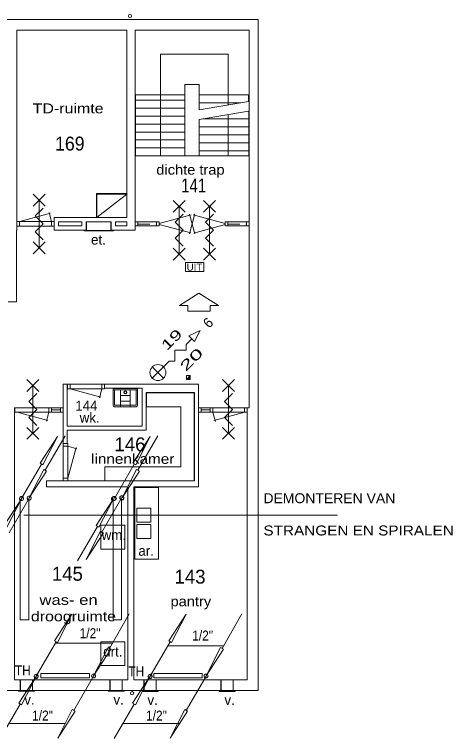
# Model space of a CAD drawing. Extents: x 295824 to 414724, y 24924 to 109024.
# Drawn here: x 326087 to 337101, y 61088 to 79286 of the extents above; entities that cross this region are included whole.
import ezdxf
from ezdxf.enums import TextEntityAlignment as Align

# ---------------------------------------------------------------- set-up
doc = ezdxf.new("R2010")
doc.units = 0
doc.header["$LTSCALE"] = 100
doc.linetypes.add('MEDIUM_DASHED', pattern=[4.5, 3, -1.5])
doc.layers.add('16', color=7, linetype='Continuous', lineweight=13)
doc.layers.add('61', color=7, linetype='Continuous', lineweight=13)

msp = doc.modelspace()

# ---------------------------------------------------------------- hatches: boundary and pattern name
at = {"layer": '61'}
msp.add_hatch(color=256, dxfattribs=at).paths.add_polyline_path([(330408.1, 70115.6), (330508.1, 70215.6), (330508.1, 70115.6)])

# ---------------------------------------------------------------- linework, layer by layer
at = {"layer": '16'}
for p, q in [((327358.8, 68694.8), (326858.8, 67828.8)), ((329690.7, 68694.8), (329190.7, 67828.8)), ((326266.2, 67121.5), (326766.2, 67987.5)), ((328598.2, 67121.5), (329098.2, 67987.5)), ((326453.4, 67125.5), (325953.4, 66259.5)), ((328785.3, 67142.2), (328285.3, 66276.2)), ((326326.3, 66702.7), (334210.4, 66702.7)), ((327675.2, 65554.4), (328175.2, 66420.4)), ((328974.5, 64220.2), (328474.5, 63354.2)), ((331804.8, 64220.2), (331304.8, 63354.2)), ((326632.7, 62655.3), (327132.7, 63521.3)), ((329501.3, 62655.3), (330001.3, 63521.3)), ((327134.2, 63488.1), (328533.4, 63488.1)), ((329943.6, 63420.8), (331342.7, 63420.8)), ((328076.8, 62658.9), (327576.8, 61792.9)), ((330904.3, 62658.9), (330404.3, 61792.9)), ((325729.6, 61087.9), (326229.6, 61953.9)), ((328592.5, 61087.9), (329092.5, 61953.9)), ((325968.1, 61468.4), (327367.3, 61468.4)), ((328816.4, 61468.4), (330215.5, 61468.4))]:
    msp.add_line(p, q, dxfattribs=at)
for points in [[(327166.2, 68680.5), (326802.2, 67966.5), (326730.2, 68008.5)], [(329498.2, 68680.5), (329134.2, 67966.5), (329062.2, 68008.5)], [(326458.8, 67135.8), (326822.8, 67849.8), (326894.8, 67807.8)], [(328790.7, 67135.8), (329154.7, 67849.8), (329226.7, 67807.8)], [(326260, 67113.4), (325896, 66399.4), (325824, 66441.4)], [(328575.2, 67113.4), (328211.2, 66399.4), (328139.2, 66441.4)], [(327885.3, 65583.2), (328249.3, 66297.2), (328321.3, 66255.2)], [(327532.7, 64214.3), (327168.7, 63500.3), (327096.7, 63542.3)], [(330401.3, 64214.3), (330037.3, 63500.3), (329965.3, 63542.3)], [(328074.5, 62661.2), (328438.5, 63375.2), (328510.5, 63333.2)], [(330904.8, 62661.2), (331268.8, 63375.2), (331340.8, 63333.2)], [(326629.6, 62646.9), (326265.6, 61932.9), (326193.6, 61974.9)], [(326752.7, 62616.5), (327969.4, 62616.5), (327969.4, 62723.7), (326752.7, 62723.7)], [(329492.5, 62646.9), (329128.5, 61932.9), (329056.5, 61974.9)], [(329590.7, 62616.5), (330807.4, 62616.5), (330807.4, 62723.7), (329590.7, 62723.7)], [(327176.8, 61099.9), (327540.8, 61813.9), (327612.8, 61771.9)], [(330004.3, 61099.9), (330368.3, 61813.9), (330440.3, 61771.9)]]:
    msp.add_lwpolyline(points, close=True, dxfattribs=at)
for points in [[(326232.5, 67104.9), (326232.5, 64071.6), (326449.1, 64071.6), (326449.1, 67088.2)], [(328564.5, 67104.9), (328564.5, 64071.6), (328781, 64071.6), (328781, 67088.2)]]:
    msp.add_lwpolyline(points, dxfattribs=at)
for centre in [(326259.9, 67113.1), (326266.2, 67121.2), (326453.4, 67125.8), (326458.8, 67136.1), (328575.2, 67113.1), (328598.1, 67121.2), (328785.3, 67142.5), (328790.7, 67136.1), (326629.6, 62646.6), (326632.7, 62655), (328074.5, 62661.5), (328076.8, 62659.2), (329492.5, 62646.6), (329501.3, 62655), (330904.3, 62659.2), (330904.8, 62661.5)]:
    msp.add_circle(centre, 50, dxfattribs=at)
at = {"layer": '61'}
for p, q in [((332210.1, 79160.8), (332210.1, 62296.5)), ((330368.9, 77267.8), (330368.9, 77525.8)), ((330368.9, 77525.8), (330732.6, 77525.8)), ((330732.6, 77267.8), (330732.6, 77525.8)), ((331972.5, 77267.8), (330732.6, 77267.8)), ((331972.5, 77100.5), (331972.5, 77267.8)), ((329129, 77131.4), (330368.9, 77131.4)), ((330732.6, 76889.3), (331972.5, 77100.5)), ((331780.5, 77067.8), (330732.6, 77067.8)), ((329129, 76931.4), (330368.9, 76931.4)), ((330729.7, 76643), (331972.5, 76854.7)), ((329129, 76731.4), (330368.9, 76731.4)), ((331975.6, 76659.4), (330826.3, 76659.4)), ((331459.8, 76767.4), (331459.8, 75733.3)), ((329129, 76531.4), (330368.9, 76531.4)), ((331975.6, 76459.4), (330729.7, 76459.4)), ((329129, 76331.4), (330368.9, 76331.4)), ((331975.6, 76259.4), (330729.7, 76259.4)), ((329129, 76131.4), (330368.9, 76131.4)), ((329129, 75931.4), (330368.9, 75931.4)), ((331975.6, 76059.4), (330729.7, 76059.4)), ((329129, 75731.4), (330368.9, 75731.4)), ((331975.6, 75859.4), (330729.7, 75859.4)), ((326857.7, 74771.3), (326557.7, 74471.3)), ((326557.7, 74771.3), (326857.7, 74471.3)), ((326707.7, 73421.3), (326707.7, 74621.3)), ((328910.1, 74785.8), (328145.1, 74785.8)), ((328145.1, 74785.8), (328145.1, 74185.8)), ((328910.1, 74770.8), (328160.1, 74770.8)), ((328160.1, 74770.8), (328160.1, 74185.8)), ((328908.7, 74765.7), (328165.8, 74191.8)), ((330376.8, 74613.9), (330076.8, 74313.9)), ((330076.8, 74613.9), (330376.8, 74313.9)), ((331143.5, 74613.9), (330843.5, 74313.9)), ((330843.5, 74613.9), (331143.5, 74313.9)), ((330226.8, 73263.9), (330226.8, 74463.9)), ((330993.5, 73263.9), (330993.5, 74463.9)), ((326218.7, 74082.5), (326991.5, 74289.6)), ((327017.1, 74083.1), (326956.4, 74310)), ((330621.8, 73771.1), (330488.5, 74268.5)), ((330489.1, 73776), (330623.8, 74278.7)), ((326142.6, 73967.9), (326142.6, 74081.9)), ((326151.2, 74081.9), (327086.5, 74081.9)), ((326210.9, 73967.9), (326210.9, 74081.9)), ((327019.5, 73967.9), (327019.5, 74081.9)), ((327086.5, 73967.9), (327086.5, 74081.9)), ((328910.1, 74185.8), (327087.4, 74185.8)), ((327087.4, 73865.8), (327087.4, 74185.8)), ((327196.2, 73975.8), (327196.2, 74075.8)), ((327780.1, 74075.8), (327196.2, 74075.8)), ((327780.1, 73975.8), (327780.1, 74075.8)), ((327890.1, 73865.8), (327890.1, 74075.8)), ((328520.1, 74075.8), (327890.1, 74075.8)), ((327895, 73859.2), (327895, 74070.9)), ((327895, 74070.9), (328510.1, 74070.9)), ((328510.1, 73859.2), (328510.1, 74070.9)), ((328520.1, 73865.8), (328520.1, 74075.8)), ((328908.2, 74075.8), (328630.1, 74075.8)), ((328630.1, 73975.8), (328630.1, 74075.8)), ((328908.2, 73975.8), (328908.2, 74075.8)), ((329120.8, 74071.5), (329723.3, 74071.5)), ((329186.3, 73971.5), (329186.3, 74071.5)), ((329657.7, 73971.5), (329657.7, 74071.5)), ((329723.3, 73971.5), (329723.3, 74071.5)), ((329725.3, 74030.5), (330529.4, 74246)), ((330578.4, 74246), (331383.5, 74030.3)), ((331384.7, 73971.5), (331384.7, 74071.5)), ((331384.7, 74071.5), (331990.1, 74071.5)), ((331451.5, 73971.6), (331451.5, 74070.6)), ((331923.1, 73971.2), (331923.1, 74071.2)), ((327086.5, 73967.9), (326151.2, 73967.9)), ((327196.2, 73975.8), (327780.1, 73975.8)), ((328630.1, 73975.8), (328908.2, 73975.8)), ((329120.8, 73971.5), (329723.3, 73971.5)), ((329723.4, 74007.3), (330517.1, 73794.6)), ((330593.7, 73792.7), (331383.5, 74004.3)), ((331384.7, 73971.5), (331990.1, 73971.5)), ((326141.5, 72065.8), (326141.5, 73865.8)), ((327087.4, 73865.8), (327890.1, 73865.8)), ((327840.7, 73858.9), (328577.6, 73858.9)), ((327840.7, 73848.9), (327840.7, 73858.9)), ((327840.7, 73848.9), (328577.6, 73848.9)), ((328520.1, 73865.8), (329120.1, 73865.8)), ((328577.6, 73848.9), (328577.6, 73858.9)), ((331990.1, 73865.8), (331990.1, 69402.2)), ((326857.7, 73571.3), (326557.7, 73271.3)), ((326557.7, 73571.3), (326857.7, 73271.3)), ((330376.8, 73413.9), (330076.8, 73113.9)), ((330076.8, 73413.9), (330376.8, 73113.9)), ((331143.5, 73413.9), (330843.5, 73113.9)), ((330843.5, 73413.9), (331143.5, 73113.9)), ((325931.5, 72065.8), (326141.5, 72065.8)), ((329835.6, 70144.4), (329552.8, 70427.2)), ((326700.5, 70108.8), (326400.5, 69808.8)), ((326400.5, 70108.8), (326700.5, 69808.8)), ((331615.3, 70108.8), (331315.3, 69808.8)), ((331315.3, 70108.8), (331615.3, 69808.8)), ((326550.5, 68758.8), (326550.5, 69958.8)), ((327315.1, 69991.5), (327315.1, 69391.5)), ((327415.1, 69991.5), (327315.1, 69991.5)), ((328353.5, 69991.7), (327418.2, 69991.7)), ((327486.5, 69991.7), (327486.5, 69877.7)), ((328286.5, 69991.7), (328286.5, 69877.7)), ((328353.5, 69991.7), (328353.5, 69877.7)), ((330715.1, 69991.5), (328354.4, 69991.5)), ((328354.4, 69891.5), (328354.4, 69991.5)), ((328354.4, 69891.5), (329295.1, 69891.5)), ((329167.9, 69887.7), (328577.9, 69887.7)), ((329295.1, 69891.5), (329295.1, 68941.5)), ((330715.1, 69391.5), (330715.1, 69991.5)), ((331465.3, 68758.8), (331465.3, 69958.8)), ((327485.7, 69877.1), (328258.4, 69670.1)), ((328284.1, 69876.5), (328223.3, 69649.6)), ((328567.9, 69877.7), (328567.9, 69462.7)), ((328577.9, 69852.7), (329167.9, 69852.7)), ((328602.9, 69477.7), (328602.9, 69837.7)), ((328752.9, 69852.7), (328752.9, 69427.7)), ((328752.9, 69711), (328992.9, 69711)), ((328992.9, 69852.7), (328992.9, 69427.7)), ((329142.9, 69837.7), (329142.9, 69477.7)), ((329177.9, 69462.7), (329177.9, 69877.7)), ((329395.1, 69781.5), (330615.1, 69781.5)), ((329407.2, 69778.6), (330608.7, 69778.6)), ((330615.1, 69781.5), (330615.1, 67566.5)), ((328752.9, 69569.4), (328992.9, 69569.4)), ((326097.9, 69402.7), (326097.9, 69288.7)), ((326954.4, 69402.7), (326954.4, 69288.7)), ((327021.4, 69402.7), (327021.4, 69288.7)), ((327247.4, 69348.6), (327021.4, 69348.6)), ((327247.4, 69402.7), (327247.4, 69288.7)), ((328602.9, 69427.7), (329142.9, 69427.7)), ((329127.9, 69462.7), (328617.9, 69462.7)), ((330780.9, 69401.2), (330780.9, 69287.2)), ((330780.9, 69347.2), (331006.9, 69347.2)), ((331006.9, 69401.2), (331006.9, 69287.2)), ((331073.9, 69401.2), (331073.9, 69287.2)), ((331873.9, 69401.2), (331873.9, 69287.2)), ((331940.1, 69402.2), (331940.1, 62566.5)), ((331990.1, 69402.2), (331940.1, 69402.2)), ((326090.1, 69291.5), (326090.1, 62566.5)), ((326153.6, 69288.1), (326926.4, 69081)), ((326952, 69287.5), (326891.3, 69060.6)), ((327315.1, 68501.8), (327315.1, 69291.5)), ((331076.3, 69286), (331137.1, 69059.1)), ((331874.7, 69286.6), (331102, 69079.6)), ((326700.5, 68908.8), (326400.5, 68608.8)), ((326400.5, 68908.8), (326700.5, 68608.8)), ((331615.3, 68908.8), (331315.3, 68608.8)), ((331315.3, 68908.8), (331615.3, 68608.8)), ((327314.7, 68501.2), (327428.7, 68501.2)), ((327314.7, 68501.2), (327314.7, 67566)), ((327314.7, 68434.2), (327428.7, 68434.2)), ((327315.1, 68501.8), (327415.1, 68501.8)), ((327430, 68431.9), (327656.8, 68371.1)), ((327429.4, 67633.5), (327636.4, 68406.2)), ((330615.1, 67566.5), (326889.8, 67566.5)), ((326889.8, 67416.5), (326889.8, 67566.5)), ((327314.7, 67634.2), (327428.7, 67634.2)), ((328940.1, 67416.5), (326889.8, 67416.5)), ((329161.9, 66878.8), (329511.9, 66878.8)), ((329512.8, 66877.1), (329512.8, 66527.1)), ((329511.9, 66524.7), (329161.9, 66524.7)), ((329161.9, 66470.6), (329511.9, 66470.6)), ((329512.8, 66468.9), (329512.8, 66118.9)), ((329511.9, 66116.4), (329161.9, 66116.4)), ((328940.1, 62566.5), (326090.1, 62566.5)), ((326233, 62296.5), (326233, 62566.5)), ((326239.4, 62291.6), (326239.4, 62566)), ((326538.1, 62291.6), (326538.1, 62566)), ((326543.7, 62296.5), (326543.7, 62566.5)), ((328486.7, 62296.5), (328486.7, 62566.5)), ((328493.2, 62291.6), (328493.2, 62566)), ((328791.9, 62291.6), (328791.9, 62566)), ((328797.4, 62296.5), (328797.4, 62566.5)), ((331940.1, 62566.5), (329090.1, 62566.5)), ((329341.8, 62286.6), (329341.8, 62556.6)), ((329348.3, 62281.8), (329348.3, 62556.1)), ((329647, 62281.8), (329647, 62556.1)), ((329652.5, 62286.6), (329652.5, 62556.6)), ((331278.1, 62286.6), (331278.1, 62556.6)), ((331284.5, 62281.8), (331284.5, 62556.1)), ((331583.2, 62281.8), (331583.2, 62556.1)), ((331588.8, 62286.6), (331588.8, 62556.6)), ((326233, 62296.5), (307806, 62296.5)), ((326190.1, 62291.6), (326588.4, 62291.6)), ((326190.1, 62276.5), (326190.1, 62291.6)), ((326190.1, 62276.5), (326588.4, 62276.5)), ((330425.5, 62296.5), (326543.7, 62296.5)), ((326588.4, 62276.5), (326588.4, 62291.6)), ((328443.9, 62291.6), (328842.2, 62291.6)), ((328443.9, 62276.5), (328443.9, 62291.6)), ((328443.9, 62276.5), (328842.2, 62276.5)), ((328842.2, 62276.5), (328842.2, 62291.6)), ((329299, 62281.8), (329697.3, 62281.8)), ((329299, 62266.7), (329299, 62281.8)), ((329299, 62266.7), (329697.3, 62266.7)), ((329697.3, 62266.7), (329697.3, 62281.8)), ((330425.5, 62296.5), (332210.1, 62296.5)), ((331235.2, 62281.8), (331633.5, 62281.8)), ((331235.2, 62266.7), (331235.2, 62281.8)), ((331235.2, 62266.7), (331633.5, 62266.7)), ((331633.5, 62266.7), (331633.5, 62281.8))]:
    msp.add_line(p, q, dxfattribs=at)
at = {"layer": '61', "linetype": 'MEDIUM_DASHED'}
for p, q in [((329188.3, 74017.9), (329658.2, 74017.9)), ((331450.5, 74015.4), (331922.9, 74015.4))]:
    msp.add_line(p, q, dxfattribs=at)
at = {"layer": '61'}
for points in [[(301796.6, 66927.7), (301820.1, 79160.8), (332210.1, 79160.8)], [(326150.1, 73853.8), (326150.1, 78890.8), (328910.1, 78890.8), (328910.1, 74185.8)], [(329120.1, 73865.8), (329120.1, 78890.8), (331990.1, 78890.8), (331990.1, 73864.1)], [(329757.2, 75731.4), (329757.2, 78292.1), (331460, 78292.1), (331460, 77013.2)], [(331972.5, 77267.8), (330732.6, 77267.8), (330732.6, 76889.3)], [(330729.7, 75733.3), (331975.6, 75733.3), (331975.6, 76859.4)], [(330729.7, 76643), (330729.7, 75733.3), (330368.9, 75731.4)], [(326807.7, 73621.3), (326607.7, 73821.3), (326807.7, 74021.3), (326607.7, 74221.3), (326807.7, 74421.3)], [(330326.8, 73463.9), (330126.8, 73663.9), (330326.8, 73863.9), (330126.8, 74063.9), (330326.8, 74263.9)], [(331093.5, 73463.9), (330893.5, 73663.9), (331093.5, 73863.9), (330893.5, 74063.9), (331093.5, 74263.9)], [(329552.8, 70144.4), (329977, 70568.7), (330118.4, 70568.7), (330118.4, 70851.5), (330401.3, 70851.5), (330401.3, 70992.9), (330542.7, 71134.3)], [(330508.1, 70215.6), (330508.1, 70115.6), (330408.1, 70115.6)], [(329295.1, 68941.5), (327415.1, 68941.5), (327415.1, 69991.5)], [(327418.2, 69991.7), (327418.2, 69877.7), (328353.5, 69877.7)], [(326650.5, 68958.8), (326450.5, 69158.8), (326650.5, 69358.8), (326450.5, 69558.8), (326650.5, 69758.8)], [(327415.1, 68501.8), (327415.1, 68841.5), (329395.1, 68841.5), (329395.1, 69781.5)], [(328361.5, 67565.7), (328361.5, 67915.7), (330267.2, 67915.7), (330267.2, 69428.6), (329407.2, 69428.6), (329407.2, 69778.6)], [(330608.7, 69778.6), (330608.7, 67565.7), (328361.5, 67565.7)], [(331565.3, 68958.8), (331365.3, 69158.8), (331565.3, 69358.8), (331365.3, 69558.8), (331565.3, 69758.8)], [(329090.1, 62566.5), (329090.1, 67416.5), (330715.1, 67416.5), (330715.1, 69291.5)], [(327314.7, 67566), (327428.7, 67566), (327428.7, 68501.2)], [(328340.1, 67416.5), (328940.1, 67416.5), (328940.1, 62566.5)], [(329113.6, 65598.8), (329708.3, 65598.8), (329708.3, 67398.8)], [(329113.6, 65598.8), (329113.6, 67398.8), (329708.3, 67398.8)], [(329162.8, 66527.1), (329162.8, 66877.1), (329161.9, 66878.8)], [(329162.8, 66118.9), (329162.8, 66468.9), (329161.9, 66470.6)]]:
    msp.add_lwpolyline(points, dxfattribs=at)
for points in [[(330368.9, 77267.8), (329129, 77267.8), (329129, 75731.4), (330368.9, 75731.4)], [(330387.6, 72825), (330847.2, 72825), (330847.2, 73049.7), (330387.6, 73049.7)], [(331003.4, 71828.6), (330443.4, 71828.6), (330443.4, 71968.6), (330233.4, 71968.6), (330723.4, 72283.6), (331213.4, 71968.6), (331003.4, 71968.6)], [(330472, 71205.1), (330613.4, 71063.7), (330754.8, 71346.5)], [(330508.1, 70215.6), (330408.1, 70215.6), (330408.1, 70115.6)], [(330408.1, 70115.6), (330508.1, 70215.6), (330508.1, 70115.6)], [(326087.4, 69402.7), (326087.4, 69288.7), (327313.8, 69288.7), (327313.8, 69402.7)], [(326087.4, 69402.7), (326087.4, 69288.7), (327313.8, 69288.7), (327313.8, 69402.7)], [(331940.9, 69401.2), (331940.9, 69287.2), (330714.6, 69287.2), (330714.6, 69401.2)], [(328258.6, 65846.1), (328258.6, 66446.1), (328863.1, 66446.1), (328863.1, 65846.1)], [(328258.6, 62921.9), (328258.6, 63521.9), (328863.1, 63521.9), (328863.1, 62921.9)]]:
    msp.add_lwpolyline(points, close=True, dxfattribs=at)
for centre, radius in [((328990.8, 79245.8), 40), ((329694.2, 70285.8), 200), ((328872.9, 69787.7), 40), ((328872.9, 69787.7), 30), ((329044.8, 62226.1), 40)]:
    msp.add_circle(centre, radius, dxfattribs=at)
for centre, radius, start, end in [((328577.9, 69877.7), 10, 90, 180), ((329167.9, 69877.7), 10, 0, 90), ((328577.9, 69862.7), 10, 180, 270), ((328617.9, 69837.7), 15, 90, 180), ((329127.9, 69837.7), 15, 0, 90), ((329167.9, 69862.7), 10, 270, 0), ((328602.9, 69462.7), 35, 180, 270), ((328617.9, 69477.7), 15, 180, 270), ((329127.9, 69477.7), 15, 270, 0), ((329142.9, 69462.7), 35, 270, 0)]:
    msp.add_arc(centre, radius, start, end, dxfattribs=at)

# ---------------------------------------------------------------- texts
at = {"layer": '16'}
for s, width, p in [('DEMONTEREN VAN', 1.05, (332346.5, 67002.1)), ('STRANGEN EN SPIRALEN', 1.15, (332346.5, 66191.8)), ('1/2"', 0.9, (327724.1, 63609.6)), ('1/2"', 0.9, (330554.8, 63550.5)), ('TH', 0.9, (326096, 62673.2)), ('TH', 0.9, (328947.1, 62649.6)), ('1/2"', 0.9, (326529.1, 61539.9)), ('1/2"', 0.9, (329394, 61539.9))]:
    msp.add_text(s, height=250, dxfattribs=dict(at, width=width)).set_placement(p)
at = {"layer": '61'}
for s, height, width, p in [('TD-ruimte', 250, 1.2, (326544.2, 76800.7)), ('dichte trap', 250, 1.1, (329652.6, 75259.5)), ('UIT', 175, 1.05, (330414.3, 72846.4)), ('linnenkamer', 250, 1.15, (328012.9, 67992)), ('was- en ', 250, 1.25, (326715.2, 64446.8)), ('pantry', 250, 1.1, (330010.5, 64411.2)), ('droogruimte', 250, 1.2, (326499, 64033.7))]:
    msp.add_text(s, height=height, dxfattribs=dict(at, width=width)).set_placement(p)
for s, width, p in [('169', 0.95, (327478.1, 75865.7)), ('141', 0.8, (330591.7, 74811.7))]:
    msp.add_text(s, height=350, dxfattribs=dict(at, width=width)).set_placement(p, align=Align.CENTER)
for s, p in [('et.', (328011.9, 73501.2)), ('wk.', (327727, 69027.2)), ('wm.', (328278.3, 66079.7)), ('ar.', (329202.1, 65681.2)), ('drt.', (328317.6, 63148.2)), ('v.', (326334.2, 61942.2)), ('v.', (328575.4, 61942.2)), ('v.', (329430.5, 61932.4)), ('v.', (331366.8, 61932.4))]:
    msp.add_text(s, height=250, dxfattribs=at).set_placement(p)
msp.add_text('6', height=250, rotation=45, dxfattribs=at).set_placement((330977.5, 71384.2))
for s, width, p in [('19', 1.55, (329921.2, 70822.7)), ('20', 1.75, (330393.5, 70294.3))]:
    msp.add_text(s, height=250, rotation=45, dxfattribs=dict(at, width=width)).set_placement(p)
for s, height, p in [('144', 250, (327893.4, 69326.9)), ('146', 350, (328989.9, 68306.4)), ('145', 350, (327416.7, 65053.7)), ('143', 350, (330499.5, 64980.7))]:
    msp.add_text(s, height=height, dxfattribs=at).set_placement(p, align=Align.CENTER)

doc.saveas('drawing.dxf')
